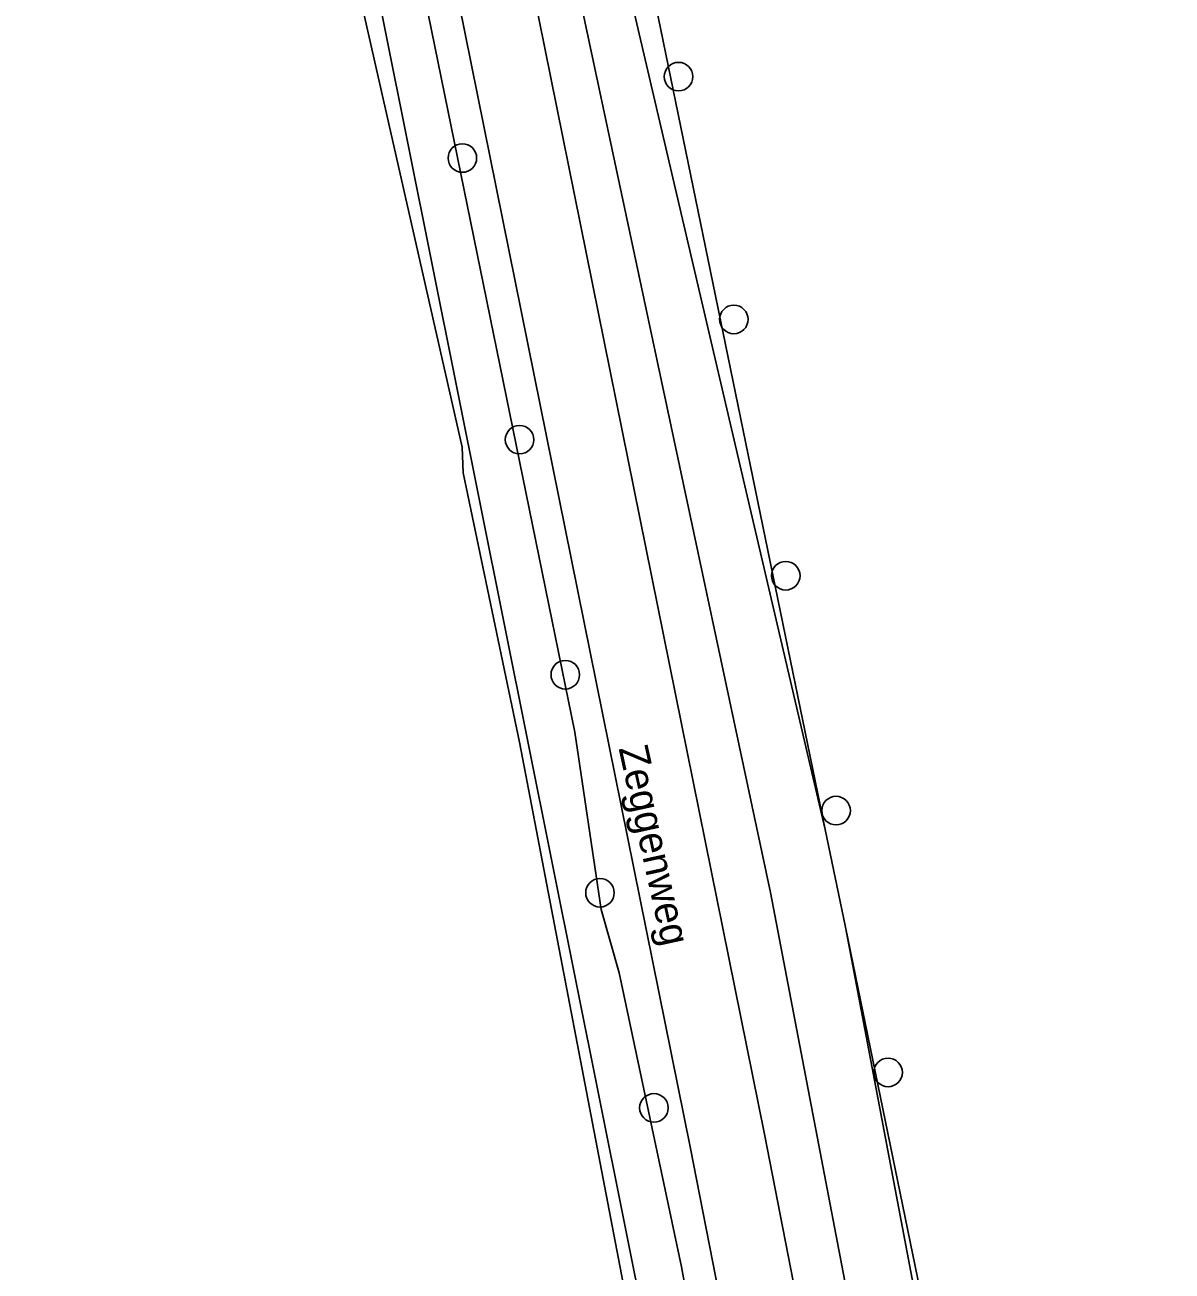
# Model space of a CAD drawing. Extents: x 164494 to 166241, y 382475 to 384495.
# Drawn here: x 165344.77 to 165384.04, y 382927.96 to 382970.64 of the extents above; entities that cross this region are included whole.
import ezdxf

# ---------------------------------------------------------------- set-up
doc = ezdxf.new("R2010")
doc.units = 0
for name, color, linetype in [('IMGEO_Boom', 7, 'Continuous'), ('IMGEO_Grasland_agrarisch', 7, 'Continuous'), ('IMGEO_Grasland_overig', 7, 'Continuous'), ('IMGEO_Groenvoorziening', 7, 'Continuous'), ('IMGEO_Hek', 7, 'Continuous'), ('IMGEO_Oever', 7, 'Continuous'), ('IMGEO_Openbare_ruimte_label', 7, 'Continuous'), ('IMGEO_Rijbaan_lokaal_gesloten', 7, 'Continuous'), ('IMGEO_Waterloop', 7, 'Continuous')]:
    doc.layers.add(name, color=color, linetype=linetype)

msp = doc.modelspace()

# ---------------------------------------------------------------- linework, layer by layer
at = {"layer": 'IMGEO_Boom'}
for centre in [(165367.143, 382968.87), (165359.743, 382966.083), (165369.037, 382960.554), (165361.7, 382956.436), (165370.815, 382951.775), (165363.267, 382948.384), (165372.537, 382943.732), (165364.455, 382940.916), (165374.318, 382934.761), (165366.302, 382933.549)]:
    msp.add_circle(centre, 0.489, dxfattribs=at)
at = {"layer": 'IMGEO_Grasland_agrarisch'}
for points in [[(165353.332, 383137.383), (165354.788, 383114.232), (165354.258, 383081.424), (165354.126, 383061.845), (165354.523, 383033.931), (165358.227, 383011.309), (165362.46, 382991.863), (165362.613, 382991.161), (165363.207, 382988.655), (165362.514, 382988.434), (165363.717, 382984.203), (165372.168, 382943.087), (165372.856, 382939.739), (165382.403, 382893.288), (165387.312, 382874.042)], [(165359.769, 382955.3), (165359.734, 382956.18), (165356.227, 382971.696)], [(165373.429, 382883.9), (165373.376, 382885.12), (165361.694, 382946.072), (165359.769, 382955.3)]]:
    msp.add_lwpolyline(points, dxfattribs=at)
at = {"layer": 'IMGEO_Grasland_overig'}
for points in [[(165384.673, 382868.78), (165385.006, 382868.982), (165383.397, 382876.479), (165381.213, 382883.79), (165370.298, 382940.925), (165362.234, 382978.755), (165362.713, 382978.926), (165363.713, 382979.283), (165372.168, 382943.087), (165363.717, 382984.203), (165362.514, 382988.434), (165360.312, 382987.732), (165352.989, 383023.828), (165352.045, 383031.273), (165351.908, 383033.035), (165351, 383044.746), (165350.836, 383059.665)], [(165347.25, 383028.216), (165348.807, 383020.428), (165350.356, 383011.321), (165352.665, 383000), (165363.594, 382946.421), (165364.499, 382940.338), (165365.106, 382938.175), (165367.246, 382928.104), (165369.474, 382915.955), (165371.094, 382908.927), (165373.333, 382895.198), (165374.389, 382890.952), (165375.785, 382883.607)], [(165350.782, 383028.125), (165356.469, 383000), (165370.087, 382932.653), (165375.491, 382904.901)], [(165367.541, 382932.219), (165353.851, 383000), (165348.277, 383027.598)], [(165374.601, 382892.957), (165374.247, 382894.542), (165373.303, 382899.751), (165372.925, 382902.961), (165372.397, 382907.454), (165367.541, 382932.219)]]:
    msp.add_lwpolyline(points, dxfattribs=at)
at = {"layer": 'IMGEO_Groenvoorziening'}
msp.add_lwpolyline([(165387.312, 382874.042), (165382.403, 382893.288), (165372.856, 382939.739), (165383.556, 382883.304), (165386.262, 382875.949), (165387.208, 382873.986)], close=True, dxfattribs=at)
at = {"layer": 'IMGEO_Hek'}
for points in [[(165372.168, 382943.087), (165363.717, 382984.203)], [(165372.856, 382939.739), (165372.168, 382943.087)], [(165387.312, 382874.042), (165382.403, 382893.288), (165372.856, 382939.739)]]:
    msp.add_lwpolyline(points, dxfattribs=at)
at = {"layer": 'IMGEO_Oever'}
for points in [[(165344.768, 383029.045), (165344.869, 383027.569), (165345.313, 383024.567), (165347.079, 383015.039), (165348.138, 383011.314), (165348.36, 383010.363), (165350.071, 383003.024), (165350.066, 383002.185), (165350.648, 383000), (165351.453, 382995.905), (165355.567, 382974.979), (165355.677, 382973.399), (165356.227, 382971.696), (165359.734, 382956.18), (165359.769, 382955.3), (165361.694, 382946.072), (165373.376, 382885.12), (165373.429, 382883.9)], [(165374.27, 382884.785), (165345.611, 383027.801)]]:
    msp.add_lwpolyline(points, dxfattribs=at)
at = {"layer": 'IMGEO_Rijbaan_lokaal_gesloten'}
for points in [[(165348.277, 383027.598), (165353.851, 383000), (165367.541, 382932.219), (165372.397, 382907.454), (165372.925, 382902.961), (165373.303, 382899.751), (165374.247, 382894.542), (165374.601, 382892.957)], [(165375.491, 382904.901), (165370.087, 382932.653), (165356.469, 383000)]]:
    msp.add_lwpolyline(points, dxfattribs=at)
at = {"layer": 'IMGEO_Waterloop'}
for points in [[(165374.389, 382890.952), (165373.333, 382895.198), (165371.094, 382908.927), (165369.474, 382915.955), (165367.246, 382928.104), (165365.106, 382938.175), (165364.499, 382940.338), (165363.594, 382946.421), (165352.665, 383000), (165350.356, 383011.321), (165348.807, 383020.428), (165347.25, 383028.216)], [(165345.611, 383027.801), (165374.27, 382884.785)]]:
    msp.add_lwpolyline(points, dxfattribs=at)
msp.add_lwpolyline([(165372.856, 382939.739), (165372.168, 382943.087), (165363.713, 382979.283), (165362.713, 382978.926), (165362.234, 382978.755), (165370.298, 382940.925), (165381.213, 382883.79), (165383.397, 382876.479), (165385.412, 382871.766), (165388.876, 382865.771), (165389.75, 382867.979), (165389.957, 382868.28), (165387.208, 382873.986), (165386.262, 382875.949), (165383.556, 382883.304)], close=True, dxfattribs=at)

# ---------------------------------------------------------------- texts
at = {"layer": 'IMGEO_Openbare_ruimte_label'}
msp.add_text('Zeggenweg', height=1, rotation=282.4108, dxfattribs=at).set_placement((165365.089, 382945.864))

doc.saveas('drawing.dxf')
